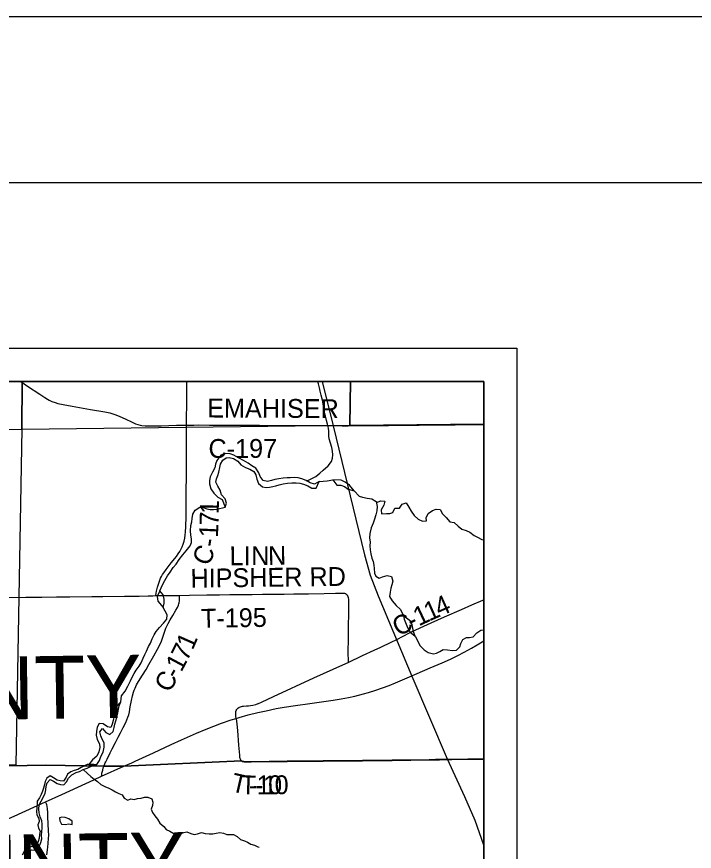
# Model space of a CAD drawing. Extents: x 0 to 45.9, y 0 to 22.
# Drawn here: x 7.492 to 9.535, y 19.483 to 22 of the extents above; entities that cross this region are included whole.
import ezdxf

# ---------------------------------------------------------------- set-up
doc = ezdxf.new("R2010")
doc.units = 0
for name, color, linetype in [('Default', 7, 'Continuous'), ('GM_X_County_Road', 7, 'Continuous'), ('GM_X_County_Road_Text', 7, 'Continuous'), ('GM_X_County_Text', 7, 'Continuous'), ('GM_X_Minor_Lake', 7, 'Continuous'), ('GM_X_Minor_River', 7, 'Continuous'), ('GM_X_Rail_Line', 7, 'Continuous'), ('GM_X_Section', 7, 'Continuous'), ('GM_X_State_Route', 7, 'Continuous'), ('GM_X_Township_Road', 7, 'Continuous'), ('GM_X_Township_Road_Text', 7, 'Continuous'), ('SH_Cut_Line', 7, 'Continuous'), ('SH_Data', 7, 'Continuous'), ('SH_Text', 7, 'Continuous')]:
    doc.layers.add(name, color=color, linetype=linetype)

msp = doc.modelspace()

# ---------------------------------------------------------------- linework, layer by layer
at = {"layer": 'Default'}
for points in [[(6.5632, 19.7246), (7.5798, 19.7427), (7.7544, 19.7392), (7.8148, 19.7399), (8.1695, 19.7557), (8.1715, 19.7545), (8.1738, 19.7539), (8.1769, 19.7536), (8.1986, 19.753), (8.3073, 19.7545), (8.3601, 19.7548), (8.416, 19.7551), (8.534, 19.7564), (8.6241, 19.7574), (8.7358, 19.7589), (8.7544, 19.7593), (8.7668, 19.7594), (8.804, 19.7598), (8.9, 19.7611), (8.9, 20.9), (5.5025, 20.9)], [(8.9, 14.1), (8.9, 19.7611), (8.804, 19.7598), (8.7668, 19.7594), (8.7544, 19.7593), (8.7358, 19.7589), (8.6241, 19.7574), (8.534, 19.7564), (8.416, 19.7551), (8.3601, 19.7548), (8.3073, 19.7545), (8.1986, 19.753), (8.1769, 19.7536), (8.1738, 19.7539), (8.1715, 19.7545), (8.1695, 19.7557), (7.8148, 19.7399), (7.7544, 19.7392), (7.5798, 19.7427), (6.5632, 19.7246)]]:
    msp.add_lwpolyline(points, dxfattribs=at)
for points in [[(7.5085, 20.9), (6.4902, 20.9), (6.4911, 20.7416), (7.5073, 20.7557)], [(8.4978, 20.9), (7.5085, 20.9), (7.5073, 20.7557), (8.4963, 20.7679)], [(8.9, 20.7722), (8.9, 20.9), (8.4978, 20.9), (8.4963, 20.7679)]]:
    msp.add_lwpolyline(points, close=True, dxfattribs=at)
at = {"layer": 'GM_X_County_Road'}
for points in [[(8.0036, 20.7684), (8.0037, 20.7719), (8.0038, 20.797), (8.0042, 20.8236), (8.0051, 20.8713), (8.0052, 20.9)], [(7.9111, 20.2539), (7.9124, 20.2615), (7.9135, 20.2677), (7.9166, 20.2798), (7.9203, 20.2917), (7.9234, 20.3006), (7.9257, 20.3064), (7.9285, 20.312), (7.9315, 20.3175), (7.9349, 20.3227), (7.9424, 20.3327), (7.9576, 20.3524), (7.9731, 20.3719), (7.9785, 20.3794), (7.9835, 20.3872), (7.9879, 20.3953), (7.9906, 20.4009), (7.9939, 20.4095), (7.9965, 20.4184), (7.9985, 20.4274), (7.9999, 20.4366), (8.0008, 20.4458), (8.0016, 20.4613), (8.0023, 20.4923), (8.0025, 20.5234), (8.0027, 20.5482), (8.003, 20.5762), (8.0035, 20.6073), (8.0034, 20.6308), (8.0036, 20.6445), (8.0038, 20.6725), (8.0039, 20.6849), (8.0036, 20.719), (8.0036, 20.7684)], [(8.0036, 20.7684), (8.0126, 20.7684), (8.0259, 20.7684), (8.0403, 20.7686), (8.0727, 20.7683), (8.1141, 20.7681), (8.1422, 20.768), (8.1685, 20.768), (8.1964, 20.7678), (8.2242, 20.7675), (8.2548, 20.7673), (8.2772, 20.7671), (8.3175, 20.7669), (8.3423, 20.7669), (8.3765, 20.7667), (8.4199, 20.7667), (8.4448, 20.7666), (8.4727, 20.7664), (8.4913, 20.7663), (8.5255, 20.7665), (8.5534, 20.7666), (8.5845, 20.7669), (8.6124, 20.7671), (8.6652, 20.7679), (8.7056, 20.7683), (8.7676, 20.7688), (8.8142, 20.7694), (8.8422, 20.7696), (8.8825, 20.77), (8.9, 20.7701)], [(7.4567, 20.248), (7.5188, 20.2489), (7.5673, 20.2495), (7.612, 20.2499), (7.6518, 20.2506), (7.7183, 20.2512), (7.7509, 20.2516), (7.8171, 20.252), (7.8419, 20.2522), (7.8605, 20.2524), (7.8884, 20.253), (7.9017, 20.2537), (7.9111, 20.2539)], [(7.7546, 19.7386), (7.7587, 19.7492), (7.7602, 19.7524), (7.7622, 19.7569), (7.7642, 19.761), (7.7731, 19.7794), (7.7797, 19.792), (7.7895, 19.8107), (7.7975, 19.8267), (7.8046, 19.8405), (7.8124, 19.8556), (7.8206, 19.8714), (7.8238, 19.8788), (7.827, 19.8874), (7.8293, 19.8945), (7.8314, 19.9036), (7.8343, 19.9188), (7.8379, 19.9376), (7.8409, 19.9512), (7.8439, 19.9628), (7.8461, 19.969), (7.8485, 19.9748), (7.8531, 19.9844), (7.8594, 19.9952), (7.8711, 20.0136), (7.882, 20.0314), (7.8904, 20.046), (7.9054, 20.0727), (7.9159, 20.0925), (7.923, 20.1055), (7.928, 20.1169), (7.9323, 20.1285), (7.9373, 20.1432), (7.9417, 20.1555), (7.9483, 20.1693), (7.9544, 20.1805), (7.9624, 20.1939), (7.972, 20.2096), (7.9766, 20.218), (7.9796, 20.2246), (7.981, 20.2288), (7.9817, 20.2317), (7.9826, 20.2378), (7.9828, 20.2547)], [(7.9111, 20.2539), (7.9331, 20.2539), (7.959, 20.2545), (7.9828, 20.2547)], [(8.4909, 20.0524), (8.5345, 20.0728), (8.5699, 20.0893), (8.5902, 20.0988), (8.6213, 20.1133), (8.638, 20.1215), (8.6574, 20.1312), (8.6766, 20.1413), (8.6955, 20.1508), (8.719, 20.1618), (8.7414, 20.1718), (8.7816, 20.1896), (8.8331, 20.2124), (8.8641, 20.226), (8.8975, 20.2406), (8.9, 20.2416)], [(8.2202, 19.9284), (8.2212, 19.9287), (8.2298, 19.9323), (8.2665, 19.9492), (8.388, 20.0057), (8.4753, 20.0451), (8.4909, 20.0524)], [(8.1532, 19.8832), (8.1526, 19.8896), (8.1522, 19.8955), (8.152, 19.8985), (8.1522, 19.9015), (8.1527, 19.9044), (8.1537, 19.9072), (8.155, 19.9099), (8.1567, 19.9123), (8.1588, 19.9144), (8.1611, 19.9162), (8.1637, 19.9176), (8.1664, 19.9188), (8.1693, 19.9196), (8.1723, 19.9202), (8.1753, 19.9205), (8.1847, 19.921), (8.1909, 19.9214), (8.1971, 19.9222), (8.2033, 19.9233), (8.2123, 19.9257), (8.2202, 19.9284)], [(7.7478, 19.7089), (7.7481, 19.7127), (7.7484, 19.7158), (7.7487, 19.7184), (7.7493, 19.7217), (7.7509, 19.7275), (7.7529, 19.734), (7.7546, 19.7386)], [(7.5789, 19.632), (7.6281, 19.6545), (7.6762, 19.6763), (7.7243, 19.6983), (7.7478, 19.7089)], [(7.5828, 19.4721), (7.5847, 19.4875), (7.5858, 19.4953), (7.5868, 19.5068), (7.5878, 19.5213), (7.5882, 19.5314), (7.5875, 19.5449), (7.5865, 19.5658), (7.5856, 19.587), (7.5853, 19.6001), (7.5846, 19.6111), (7.5839, 19.6186), (7.5827, 19.6231), (7.5815, 19.6259), (7.5789, 19.632)]]:
    msp.add_lwpolyline(points, dxfattribs=at)
at = {"layer": 'GM_X_Minor_Lake'}
for points in [[(7.6591, 19.5674), (7.659, 19.5735), (7.649, 19.581), (7.6374, 19.5851), (7.6276, 19.5861), (7.6203, 19.584)], [(7.6203, 19.584), (7.6216, 19.5745), (7.627, 19.5645), (7.6383, 19.5638), (7.6486, 19.5658), (7.6592, 19.564), (7.6591, 19.5674)]]:
    msp.add_lwpolyline(points, dxfattribs=at)
at = {"layer": 'GM_X_Minor_River'}
msp.add_line((7.7246, 19.7443), (7.7041, 19.7441), dxfattribs=at)
for points in [[(8.3657, 20.6), (8.3718, 20.6024), (8.3814, 20.6071), (8.3936, 20.6133), (8.4055, 20.623), (8.416, 20.6319), (8.431, 20.6456), (8.4411, 20.6583), (8.4444, 20.6685), (8.445, 20.6783), (8.4437, 20.6894), (8.4416, 20.7008), (8.4381, 20.7138), (8.4342, 20.7264), (8.4333, 20.7363), (8.4325, 20.7496), (8.4315, 20.7591), (8.4287, 20.771), (8.426, 20.7824), (8.4224, 20.7947), (8.42, 20.805), (8.4176, 20.8172), (8.416, 20.832), (8.414, 20.8438), (8.4101, 20.8587), (8.407, 20.8702), (8.4045, 20.8805), (8.4014, 20.8923), (8.3998, 20.9)], [(8.4039, 20.5979), (8.3901, 20.5899), (8.3765, 20.5939), (8.3646, 20.6006), (8.3511, 20.6066), (8.3409, 20.6091), (8.3299, 20.6101), (8.3167, 20.6096), (8.3072, 20.6091), (8.295, 20.6078), (8.2818, 20.6058), (8.27, 20.6038), (8.2605, 20.6013), (8.2483, 20.5981), (8.2347, 20.6007), (8.2259, 20.6134), (8.2219, 20.6245), (8.2124, 20.6384), (8.2012, 20.6455), (8.1892, 20.6533), (8.1754, 20.6612), (8.1608, 20.6691), (8.1462, 20.6774), (8.1349, 20.6814), (8.1202, 20.6821), (8.1076, 20.677), (8.0955, 20.6613), (8.0915, 20.6504), (8.0894, 20.6391), (8.0826, 20.6263), (8.0748, 20.612), (8.0734, 20.601), (8.0728, 20.5908), (8.0767, 20.5763), (8.0862, 20.5624), (8.0977, 20.5512), (8.1108, 20.5437), (8.1206, 20.5207)], [(8.1206, 20.5207), (8.1242, 20.5331), (8.1199, 20.5454), (8.1092, 20.5577), (8.1053, 20.5715), (8.0977, 20.5838), (8.0926, 20.5961), (8.0943, 20.6063), (8.098, 20.6165), (8.1012, 20.6263), (8.1041, 20.6403), (8.1066, 20.6505), (8.113, 20.6629), (8.1229, 20.6691), (8.1328, 20.6704), (8.1452, 20.6679), (8.1583, 20.6589), (8.1679, 20.6488), (8.1818, 20.6402), (8.1945, 20.635), (8.2072, 20.6279), (8.2127, 20.6183), (8.2162, 20.6053), (8.2205, 20.5919), (8.2328, 20.5821), (8.2437, 20.58), (8.2536, 20.5806), (8.2639, 20.583), (8.2734, 20.5851), (8.2833, 20.5879), (8.2947, 20.5907), (8.308, 20.5935), (8.3209, 20.5943), (8.3341, 20.5944), (8.3451, 20.5927), (8.3568, 20.5902), (8.3695, 20.5846), (8.3815, 20.5783), (8.3951, 20.5776), (8.4039, 20.5979)], [(8.4039, 20.5979), (8.4274, 20.6001), (8.4449, 20.6031)], [(8.4449, 20.6031), (8.4567, 20.5866), (8.4688, 20.5867), (8.4804, 20.5834), (8.4909, 20.5752), (8.5089, 20.5698)], [(8.5089, 20.5698), (8.4953, 20.5873), (8.4826, 20.5963), (8.4706, 20.6022), (8.4449, 20.6031)], [(8.5089, 20.5698), (8.5245, 20.554), (8.5347, 20.5511), (8.549, 20.5482), (8.5622, 20.5456), (8.5756, 20.5377), (8.5791, 20.5229), (8.5773, 20.51), (8.5748, 20.4979), (8.5711, 20.4847), (8.5667, 20.4726), (8.5607, 20.4587), (8.557, 20.4417), (8.5559, 20.4284), (8.5575, 20.4147), (8.5569, 20.4037), (8.5574, 20.3923), (8.5591, 20.3797), (8.5626, 20.3671), (8.5661, 20.3568), (8.5682, 20.3457), (8.5695, 20.3358), (8.5711, 20.3217), (8.5747, 20.3122), (8.5848, 20.307), (8.5951, 20.3102), (8.6092, 20.3145), (8.6216, 20.3116), (8.6259, 20.2974), (8.623, 20.2861), (8.6197, 20.2759), (8.6176, 20.2646), (8.6162, 20.2513), (8.6235, 20.2378), (8.636, 20.2243), (8.6487, 20.2123), (8.6581, 20.1931)], [(7.9233, 20.2688), (7.9316, 20.2865), (7.9383, 20.2993), (7.9465, 20.3131), (7.9544, 20.3251), (7.9637, 20.3386), (7.9723, 20.3487), (7.9813, 20.3629), (7.9922, 20.3764), (8.0031, 20.3894), (8.0143, 20.4036), (8.0191, 20.4138), (8.019, 20.4252), (8.0165, 20.4363), (8.0153, 20.4488), (8.0168, 20.4651), (8.0197, 20.4761), (8.021, 20.4863), (8.0232, 20.4995), (8.0299, 20.5115), (8.0437, 20.5208), (8.0543, 20.5198), (8.0648, 20.5161), (8.0753, 20.5133), (8.0856, 20.5134), (8.0951, 20.5147), (8.1206, 20.5207)], [(8.5764, 20.5344), (8.5897, 20.5397), (8.6018, 20.5383), (8.5989, 20.5266), (8.591, 20.5131), (8.5915, 20.501), (8.6067, 20.5014), (8.6165, 20.502), (8.6261, 20.5048), (8.632, 20.5176), (8.6456, 20.5177), (8.6542, 20.5297), (8.6657, 20.5336), (8.6737, 20.5205), (8.6807, 20.5086), (8.6906, 20.4951), (8.7025, 20.4846), (8.7149, 20.4786), (8.727, 20.4791), (8.7264, 20.4886), (8.732, 20.5018), (8.7451, 20.5103), (8.7569, 20.515), (8.7686, 20.5136), (8.7752, 20.5005), (8.787, 20.4897), (8.7974, 20.4769), (8.8106, 20.4747), (8.8225, 20.4631), (8.8336, 20.4541), (8.8472, 20.4504), (8.8577, 20.4449), (8.8711, 20.4355), (8.8812, 20.4303), (8.8939, 20.4232), (8.9, 20.422)], [(7.9233, 20.2688), (7.9149, 20.2511), (7.9169, 20.2374), (7.9336, 20.2181)], [(7.9336, 20.2181), (7.9361, 20.2313), (7.936, 20.2431), (7.9332, 20.2561), (7.9233, 20.2688)], [(7.8053, 19.934), (7.8079, 19.9518), (7.8188, 19.9653), (7.8267, 19.981), (7.8346, 19.9972), (7.8413, 20.0096), (7.8457, 20.0194), (7.852, 20.0295), (7.8605, 20.0411), (7.8668, 20.0516), (7.8728, 20.0648), (7.8779, 20.0761), (7.8835, 20.0866), (7.8894, 20.1001), (7.8949, 20.1106), (7.8998, 20.1238), (7.9057, 20.1355), (7.9123, 20.1456), (7.9221, 20.1576), (7.9348, 20.1706), (7.9445, 20.1825), (7.9452, 20.1962), (7.9336, 20.2181)], [(8.6581, 20.1931), (8.6605, 20.1831), (8.6641, 20.1724), (8.6706, 20.1575), (8.6786, 20.1433), (8.6935, 20.1319)], [(8.6935, 20.1319), (8.6885, 20.1442), (8.6861, 20.156), (8.684, 20.1659), (8.6797, 20.1755), (8.6581, 20.1931)], [(8.6935, 20.1319), (8.7081, 20.102), (8.7207, 20.0904), (8.7326, 20.0825), (8.7481, 20.0784), (8.7576, 20.0801), (8.7672, 20.0856), (8.7775, 20.0911), (8.7911, 20.0908), (8.8062, 20.0882), (8.818, 20.0891), (8.8277, 20.0995), (8.8309, 20.1097), (8.8368, 20.1217), (8.8479, 20.1272), (8.8574, 20.1278), (8.8677, 20.1291), (8.8789, 20.1421), (8.8916, 20.1495), (8.9, 20.1508)], [(7.8053, 19.934), (7.7909, 19.9176), (7.7876, 19.904), (7.7854, 19.8911), (7.7825, 19.8768), (7.7796, 19.8658), (7.776, 19.856), (7.7651, 19.8585), (7.7527, 19.8675), (7.7406, 19.8681), (7.7344, 19.8569), (7.7318, 19.8444), (7.7312, 19.8334), (7.7347, 19.82), (7.7416, 19.8066), (7.7425, 19.7959), (7.7396, 19.7831), (7.7329, 19.7696), (7.7198, 19.7584), (7.7094, 19.7441)], [(7.7333, 19.7444), (7.7409, 19.7565), (7.7457, 19.7685), (7.7521, 19.7821), (7.7558, 19.7972), (7.7553, 19.8097), (7.7495, 19.8212), (7.7455, 19.8312), (7.7428, 19.843), (7.7506, 19.8535), (7.7609, 19.8411), (7.7729, 19.8348), (7.7825, 19.8437), (7.7851, 19.8558), (7.7879, 19.866), (7.7908, 19.8766), (7.7937, 19.8864), (7.797, 19.9008), (7.7991, 19.9114), (7.8008, 19.9216), (7.8053, 19.934)], [(7.7041, 19.7441), (7.6959, 19.7407), (7.6859, 19.7357), (7.6759, 19.7299), (7.6652, 19.7264), (7.6545, 19.7225), (7.6444, 19.7156), (7.6411, 19.7058), (7.6329, 19.6946), (7.623, 19.6949), (7.6132, 19.6974), (7.6024, 19.7038), (7.5928, 19.7105), (7.5827, 19.7036), (7.5772, 19.6935), (7.575, 19.6837), (7.5724, 19.6735), (7.5699, 19.6637), (7.5658, 19.6536), (7.5603, 19.6438), (7.5535, 19.6334), (7.5529, 19.6239), (7.5526, 19.6137), (7.5512, 19.6027), (7.5524, 19.5924), (7.5582, 19.582), (7.5598, 19.5721), (7.5557, 19.5623), (7.5574, 19.5527), (7.5624, 19.5431), (7.5606, 19.5333), (7.5595, 19.5219), (7.5562, 19.5121), (7.5518, 19.5016), (7.5422, 19.4988), (7.5327, 19.4949), (7.5228, 19.4941), (7.5153, 19.4844), (7.5085, 19.4713)], [(7.5196, 19.4733), (7.5263, 19.4837), (7.5358, 19.4869), (7.546, 19.4858), (7.556, 19.4882), (7.5608, 19.4991), (7.5649, 19.5089), (7.5678, 19.5202), (7.5666, 19.5308), (7.5677, 19.5422), (7.5683, 19.5528), (7.5683, 19.5642), (7.5674, 19.5749), (7.5628, 19.5864), (7.559, 19.5983), (7.5589, 19.6097), (7.5597, 19.623), (7.5657, 19.6338), (7.5725, 19.6469), (7.5777, 19.6578), (7.5795, 19.668), (7.5805, 19.679), (7.5835, 19.6892), (7.5928, 19.6995), (7.6025, 19.6939), (7.6133, 19.6868), (7.6239, 19.6842), (7.6337, 19.6828), (7.6423, 19.6925), (7.6482, 19.7033), (7.6576, 19.7129), (7.6714, 19.7205), (7.681, 19.7237), (7.6918, 19.7294), (7.7044, 19.7333), (7.7236, 19.7426), (7.7246, 19.7443)], [(7.7094, 19.7441), (7.7333, 19.7444)], [(7.6918, 19.7294), (7.7047, 19.7177), (7.715, 19.7087), (7.725, 19.7), (7.7358, 19.6929), (7.7454, 19.6843), (7.7577, 19.6779), (7.7693, 19.673), (7.7794, 19.6678), (7.7891, 19.6618), (7.7996, 19.6569), (7.8097, 19.6532), (7.8159, 19.6432), (7.8263, 19.6372), (7.8359, 19.6407), (7.846, 19.6393), (7.8563, 19.6421), (7.8673, 19.6429), (7.8769, 19.6457), (7.8875, 19.6458), (7.8987, 19.6405), (7.9022, 19.6309), (7.9008, 19.6211), (7.8971, 19.6102), (7.901, 19.5998), (7.9083, 19.5897), (7.916, 19.5796), (7.9228, 19.568), (7.9351, 19.5578), (7.9424, 19.5481), (7.9532, 19.5436), (7.9651, 19.5365), (7.9754, 19.537), (7.9856, 19.5359), (7.9955, 19.5394), (8.005, 19.5411), (8.0166, 19.5362), (8.0264, 19.5329), (8.0367, 19.5352), (8.0485, 19.5395), (8.0602, 19.5365), (8.0719, 19.5358), (8.0833, 19.5351), (8.0936, 19.5378), (8.1042, 19.5394), (8.1155, 19.5369), (8.1256, 19.5335), (8.1358, 19.5332), (8.1453, 19.5337), (8.1569, 19.5277), (8.1669, 19.5187), (8.1781, 19.5138), (8.1879, 19.5105), (8.1979, 19.5046), (8.2084, 19.5012), (8.2189, 19.4964), (8.2227, 19.4955)]]:
    msp.add_lwpolyline(points, dxfattribs=at)
at = {"layer": 'GM_X_Rail_Line'}
for points in [[(8.4124, 20.9), (8.4462, 20.7662), (8.5401, 20.3764), (8.5574, 20.3156), (8.5819, 20.2529), (8.6832, 20.0109), (8.7895, 19.7619)], [(8.7895, 19.7619), (8.8421, 19.6478), (8.8728, 19.577), (8.8992, 19.5018), (8.9, 19.4987)]]:
    msp.add_lwpolyline(points, dxfattribs=at)
at = {"layer": 'GM_X_Section'}
msp.add_lwpolyline([(6.4911, 20.7416), (7.5073, 20.7557), (7.4888, 19.7433), (6.557, 19.7334), (6.4896, 19.732)], close=True, dxfattribs=at)
at = {"layer": 'GM_X_State_Route'}
msp.add_line((7.7478, 19.7089), (7.815, 19.7394), dxfattribs=at)
for points in [[(7.815, 19.7394), (7.8384, 19.7499), (7.8484, 19.7543), (7.904, 19.7801), (7.9578, 19.8045), (7.9888, 19.8187), (8.0342, 19.839), (8.0628, 19.8512), (8.0858, 19.8603), (8.1092, 19.8688), (8.1386, 19.8788), (8.1532, 19.8832), (8.1623, 19.8862), (8.1892, 19.8938), (8.2192, 19.9014), (8.2435, 19.9068), (8.2739, 19.913), (8.2984, 19.9172), (8.3321, 19.9223), (8.3752, 19.9283), (8.4459, 19.9383), (8.4705, 19.9422), (8.4919, 19.9463), (8.5118, 19.9509), (8.5378, 19.9574), (8.5522, 19.9613), (8.575, 19.9688), (8.5949, 19.976), (8.6144, 19.9832), (8.6341, 19.9909), (8.6764, 20.0092), (8.7388, 20.0357), (8.7745, 20.0511), (8.7995, 20.0623), (8.8218, 20.0732), (8.8411, 20.0833), (8.8629, 20.0952), (8.8807, 20.1056), (8.9, 20.1171)], [(7.5789, 19.632), (7.6281, 19.6545), (7.6762, 19.6763), (7.7243, 19.6983), (7.7478, 19.7089)], [(7.4519, 19.5741), (7.4839, 19.5886), (7.5789, 19.632)]]:
    msp.add_lwpolyline(points, dxfattribs=at)
at = {"layer": 'GM_X_Township_Road'}
for points in [[(7.5039, 20.9), (7.5247, 20.8859), (7.5618, 20.8612), (7.5767, 20.851), (7.5848, 20.846), (7.5897, 20.8431), (7.598, 20.8393), (7.6077, 20.8359), (7.616, 20.8337), (7.6315, 20.8305), (7.659, 20.8251), (7.7139, 20.8155), (7.7571, 20.8078), (7.7723, 20.8048), (7.7818, 20.8022), (7.7907, 20.7992), (7.8022, 20.7945), (7.8191, 20.7866), (7.8396, 20.7767), (7.8504, 20.7722), (7.8574, 20.7695), (7.8637, 20.7677), (7.8695, 20.7666), (7.879, 20.7657), (7.8886, 20.7655), (7.9116, 20.766), (7.9271, 20.7663), (7.9737, 20.7681), (7.9926, 20.7684), (8.0036, 20.7684)], [(7.9828, 20.2547), (8.0132, 20.2553), (8.0655, 20.2559), (8.1032, 20.2564), (8.134, 20.257), (8.1461, 20.2572)], [(8.1461, 20.2572), (8.1682, 20.2574), (8.202, 20.2576), (8.2331, 20.2578), (8.2485, 20.2578), (8.2719, 20.258), (8.2982, 20.2584), (8.3278, 20.2592), (8.3716, 20.259), (8.4188, 20.2602), (8.453, 20.2609), (8.4627, 20.2613)], [(8.4627, 20.2613), (8.4695, 20.2615), (8.4763, 20.2613), (8.4799, 20.2609), (8.4832, 20.2598), (8.4854, 20.2584), (8.4877, 20.2564), (8.4895, 20.2538), (8.4907, 20.2509), (8.4914, 20.2479), (8.492, 20.2418), (8.4919, 20.2044), (8.4914, 20.1577), (8.4912, 20.1266), (8.4907, 20.0799), (8.4909, 20.0581), (8.4909, 20.0524)], [(8.1532, 19.8832), (8.1553, 19.8661), (8.1572, 19.8475), (8.161, 19.8027), (8.1631, 19.7728), (8.1638, 19.7667), (8.1646, 19.7637), (8.1653, 19.7614), (8.1664, 19.7589), (8.168, 19.7569), (8.1697, 19.7551)], [(8.1697, 19.7551), (8.1717, 19.754), (8.1741, 19.7534), (8.1771, 19.753), (8.188, 19.7528)], [(8.188, 19.7528), (8.1988, 19.7525), (8.3075, 19.7539), (8.3603, 19.7542), (8.4162, 19.7546), (8.5342, 19.7558), (8.6243, 19.7569), (8.736, 19.7583), (8.7546, 19.7587), (8.767, 19.7588), (8.8043, 19.7592), (8.9, 19.7605)]]:
    msp.add_lwpolyline(points, dxfattribs=at)
at = {"layer": 'SH_Cut_Line'}
for p, q in [((2, 21), (9, 21)), ((9, 21), (9, 14)), ((2.1, 20.9), (8.9, 20.9)), ((8.9, 20.9), (8.9, 14.1))]:
    msp.add_line(p, q, dxfattribs=at)
at = {"layer": 'SH_Data'}
msp.add_lwpolyline([(1.5, 21.5), (33.5, 21.5), (33.5, 0.5), (1.5, 0.5)], close=True, dxfattribs=at)
at = {"layer": 'SH_Text'}
msp.add_lwpolyline([(0, 0), (34, 0), (34, 22), (0, 22)], close=True, dxfattribs=at)
for points in [[(6.5632, 19.7246), (7.5798, 19.7427), (7.7544, 19.7392), (7.8148, 19.7399), (8.1695, 19.7557), (8.1715, 19.7545), (8.1738, 19.7539), (8.1769, 19.7536), (8.1986, 19.753), (8.3073, 19.7545), (8.3601, 19.7548), (8.416, 19.7551), (8.534, 19.7564), (8.6241, 19.7574), (8.7358, 19.7589), (8.7544, 19.7593), (8.7668, 19.7594), (8.804, 19.7598), (8.9, 19.7611), (8.9, 20.9), (2.1, 20.9)], [(8.9, 14.1), (8.9, 19.7611), (8.804, 19.7598), (8.7668, 19.7594), (8.7544, 19.7593), (8.7358, 19.7589), (8.6241, 19.7574), (8.534, 19.7564), (8.416, 19.7551), (8.3601, 19.7548), (8.3073, 19.7545), (8.1986, 19.753), (8.1769, 19.7536), (8.1738, 19.7539), (8.1715, 19.7545), (8.1695, 19.7557), (7.8148, 19.7399), (7.7544, 19.7392), (7.5798, 19.7427), (6.5632, 19.7246)]]:
    msp.add_lwpolyline(points, dxfattribs=at)

# ---------------------------------------------------------------- texts
at = {"layer": 'GM_X_County_Road_Text'}
for s, height, rotation, p in [('EMAHISER', 0.05682, 359.7316, (8.066, 20.7912)), ('C-197', 0.05682, 0, (8.07, 20.6693)), ('1', 0.0568, 88.6866, (8.1007, 20.4995)), ('7', 0.0568, 88.6288, (8.0999, 20.4644)), ('1', 0.0568, 87.3068, (8.0982, 20.428)), ('-', 0.0568, 80.3425, (8.0935, 20.3975)), ('C', 0.0568, 66.0121, (8.07, 20.3401)), ('4', 0.0568, 23.89, (8.7667, 20.1895)), ('1', 0.0568, 25.2165, (8.7039, 20.1607)), ('1', 0.0568, 24.0312, (8.7351, 20.1754)), ('C', 0.0568, 26.8476, (8.6424, 20.1296)), ('-', 0.0568, 26.8296, (8.6837, 20.1505)), ('1', 0.0568, 66.2879, (8.0221, 20.0873)), ('7', 0.0568, 63.636, (8.0053, 20.0534)), ('1', 0.0568, 61.932, (7.988, 20.0208)), ('C', 0.0568, 60.0765, (7.9523, 19.9583)), ('-', 0.0568, 60.6001, (7.9759, 19.9992))]:
    msp.add_text(s, height=height, rotation=rotation, dxfattribs=at).set_placement(p)
at = {"layer": 'GM_X_County_Text'}
for s, rotation, p in [('MARION COUNTY', 0.8268, (5.7168, 19.8552)), ('MORROW COUNTY', 0.8203, (5.6522, 19.3177))]:
    msp.add_text(s, height=0.189394, rotation=rotation, dxfattribs=at).set_placement(p)
at = {"layer": 'GM_X_Township_Road_Text'}
for s, height, rotation, p in [('L', 0.0568, 0.2914, (8.1334, 20.3454)), ('I', 0.0568, 0.2888, (8.1759, 20.3456)), ('N', 0.0568, 0.2909, (8.1992, 20.3457)), ('N', 0.0568, 1.0011, (8.25, 20.346)), ('HIPSHER RD', 0.05682, 0.7087, (8.016, 20.2777)), ('T-195', 0.05682, 0.8258, (8.0477, 20.1569)), ('T', 0.0568, 347.1821, (8.1347, 19.6644)), ('T', 0.0568, 358.3069, (8.1662, 19.6554)), ('1', 0.0568, 0.6557, (8.2151, 19.6543)), ('1', 0.0568, 0.7297, (8.2346, 19.6542)), ('0', 0.0568, 0.8585, (8.2503, 19.6547)), ('0', 0.0568, 0.8697, (8.2698, 19.6547)), ('-', 0.0568, 2.1196, (8.1922, 19.6534)), ('-', 0.0568, 0.2246, (8.2108, 19.6541))]:
    msp.add_text(s, height=height, rotation=rotation, dxfattribs=at).set_placement(p)

doc.saveas('drawing.dxf')
